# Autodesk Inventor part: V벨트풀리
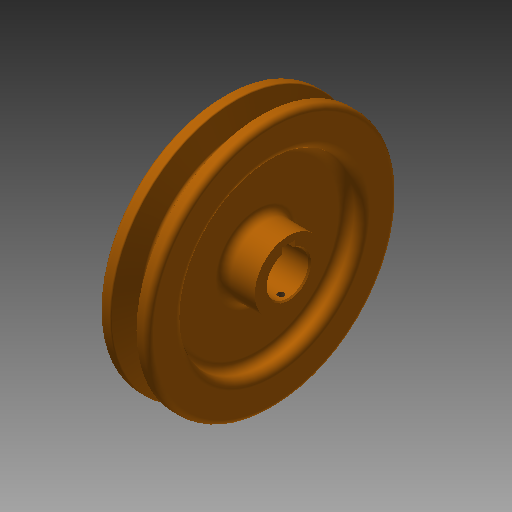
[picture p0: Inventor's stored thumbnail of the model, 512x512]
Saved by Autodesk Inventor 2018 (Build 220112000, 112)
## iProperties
Created: 2015-11
Part Number: V벨트풀리
Material: 강철, 탄소
Document SubType Name: Modeling
Designer: mduedu
Density: 1 g/cm^3
Appearance: 주황색
Author: mduedu
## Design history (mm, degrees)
sketch "스케치1"
  geometry: L1 (-9.5, 0)-(9.5, 0); L2 (0, 0)-(0, 47.7); L3 (-4.877, 47.7)-(-9.5, 47.7); L4 (-9.5, 47.7)-(-9.5, 0); L5 (0, 38.7)-(-1.953, 38.7); L6 (-1.953, 38.7)-(-4.877, 47.7); L7 (4.877, 47.7)-(9.5, 47.7); L8 (9.5, 47.7)-(9.5, 0); L9 (0, 38.7)-(1.953, 38.7); L10 (1.953, 38.7)-(4.877, 47.7); L11 (-9.5, 45)-(9.5, 45); 3 further points
  constraints: 22 end point, 7 point on line, 4 perpendicular, 3 symmetric about line, 1 coincident, 1 horizontal, 1 horizontal alignment, 1 midpoint, 1 vertical
  dimensions: "d0" = 19 distance of L1.start L1.end; "d2" = 95.4 diameter of L2.end L1 (derived); "d3" = 36 deg angle of L10 L6; "d4" = 6.3 distance between parallel lines of L11 L9; "d5" = 2.7 distance between parallel lines of L7 L11; "d6" = 8 distance of point (4, 45) point (-4, 45); "d7" = 90 diameter of L11 L1
revolve "회전1" sketch "스케치1" stored, may be unused: angle "d8" = 90 deg
sketch "스케치2"
  geometry: C1 r 34 at (0, 0); C2 r 13 at (0, 0); 1 further point
  constraints: 2 centre point, 2 coincident
  dimensions: "d9" = 68 diameter of C1; "d10" = 26 diameter of C2
extrude "돌출1" cut sketch "스케치2" distance "d11" = 6; taper "d12" = 0 deg
extrude "돌출3" join sketch "스케치2" distance "d37" = 6; taper "d38" = 0 deg
fillet "모깎기1" dims "d13" = 3
fillet "모깎기2" dims "d14" = 3
fillet "모깎기3" dims "d15" = 1, "d16" = 0.5, "d17" = 2
hole "구멍1" diameter "d20" = 16; stored, may be unused: countersink angle "d24" = 90 deg, drill point angle "d26" = 118 deg; dims "d21" = 6, "d22" = 4, "d23" = 2, "d25" = 8, "d53" = 10, "d54" = 10
sketch "스케치3"
  geometry: L1 (-2.5, 0)-(2.5, 0); L2 (2.5, 0)-(2.5, 10.3); L3 (2.5, 10.3)-(-2.5, 10.3); L4 (-2.5, 10.3)-(-2.5, 0); 2 further points
  constraints: 8 end point, 2 parallel, 1 coincident, 1 horizontal, 1 midpoint, 1 perpendicular
  dimensions: "d27" = 5 distance of L2.end L3.end; "d29" = 10.3 distance of L3.end L1.start
extrude "돌출2" cut sketch "스케치3" extent not by distance; stored distance "d30" = 6; taper "d31" = 0 deg
node "작업 평면1"
sketch "스케치4"
  geometry: L1 (19, -37)-(19, 37) reference; 2 further points
  constraints: 1 horizontal alignment
  dimensions: "d52" = 22 distance from line of L1 point (-3, 0)
hole "구멍2" sketch "스케치4" at (-3, 0) diameter "d42" = 2.459; stored, may be unused: countersink angle "d46" = 90 deg, drill point angle "d48" = 118 deg; dims "d43" = 6, "d44" = 4, "d45" = 2, "d47" = 8
chamfer "모따기3" distance "d58" = 0.5; stored, may be unused: second distance "d59" = 2, angle "d60" = 45 deg
node "솔리드1"
mirror "대칭1"
